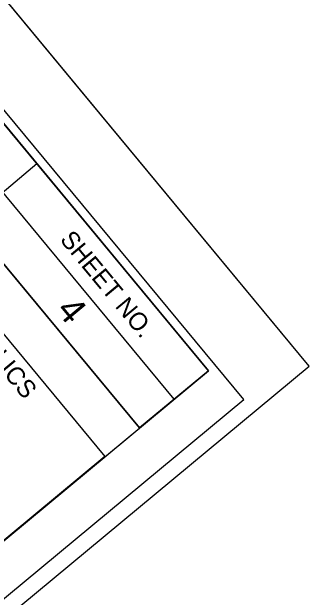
# Model space of a CAD drawing. Extents: x 2057815 to 2059783, y 687683 to 689713.
# Drawn here: x 2059649.4 to 2059732.6, y 688317.6 to 688481 of the extents above; entities that cross this region are included whole.
import ezdxf

# ---------------------------------------------------------------- set-up
doc = ezdxf.new("R2010")
doc.units = 0
for name, color, linetype in [('Sheet Cutting Line CELL', 7, 'Continuous'), ('Sheet Data Field CELL', 7, 'Continuous'), ('Sheet Plan CELL', 7, 'Continuous'), ('Sheet Plan Layout CELL', 7, 'Continuous'), ('Sheet Plot Border Inside CELL', 7, 'Continuous'), ('Sheet Plot Border Outside CELL', 7, 'Continuous')]:
    doc.layers.add(name, color=color, linetype=linetype)

msp = doc.modelspace()

# ---------------------------------------------------------------- linework, layer by layer
at = {"layer": 'Sheet Cutting Line CELL'}
msp.add_line((2059732.58, 688382.1), (2058657.95, 689678), dxfattribs=at)
at = {"layer": 'Sheet Plan CELL'}
for p, q in [((2059567.06, 688526.83), (2059694.75, 688372.83)), ((2059557.41, 688518.82), (2059685.12, 688364.85)), ((2059557.41, 688518.82), (2059685.12, 688364.85)), ((2059656.47, 688438.56), (2059637.26, 688422.56))]:
    msp.add_line(p, q, dxfattribs=at)
for points in [[(2059704.43, 688380.81), (2058746.91, 689535.49), (2057938.66, 688865.25), (2058896.16, 687710.59)], [(2059576.73, 688534.83), (2059704.43, 688380.81), (2059685.12, 688364.85), (2059557.41, 688518.82)], [(2059611.67, 688433.83), (2059675.5, 688356.87), (2059588.9, 688285.05), (2059525.06, 688362.01)]]:
    msp.add_lwpolyline(points, close=True, dxfattribs=at)
at = {"layer": 'Sheet Plan Layout CELL'}
msp.add_lwpolyline([(2059388.89, 688430.01), (2059541.63, 688245.83), (2059704.44, 688380.81), (2059551.69, 688565.01)], close=True, dxfattribs=at)
at = {"layer": 'Sheet Plot Border Inside CELL'}
msp.add_lwpolyline([(2057838.75, 688981.79), (2058902.21, 687699.38), (2059714.31, 688372.8), (2058650.85, 689655.23)], close=True, dxfattribs=at)
at = {"layer": 'Sheet Plot Border Outside CELL'}
msp.add_lwpolyline([(2057815.06, 688979.03), (2058889.68, 687683.13), (2059732.58, 688382.1), (2058657.95, 689678)], close=True, dxfattribs=at)

# ---------------------------------------------------------------- texts
at = {"layer": 'Sheet Data Field CELL'}
msp.add_text('4', height=7.5, rotation=309.6672, dxfattribs=at).set_placement((2059661.61, 688397.6))
at = {"layer": 'Sheet Plan CELL'}
for s, p in [('SHEET NO.', (2059662.71, 688417.3)), ('HYDRAULICS', (2059625.51, 688405.74))]:
    msp.add_text(s, height=5, rotation=309.6672, dxfattribs=at).set_placement(p)

doc.saveas('drawing.dxf')
